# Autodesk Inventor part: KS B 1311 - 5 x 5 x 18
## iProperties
IsCustomPart: 0
Created: 2009-02
Part Number: KS B 1311 - 5 x 5 x 18
Material: 강, 연강
Description: 키 및 해당 키홈
Document SubType Name: Modeling
Standard: KS B 1311
Designer: KYOUNG IL JANG
Standards Organization: KS
Language: ko-KR
Size Designation: 5 x 5 x 18
Categories: <MemberInstance><Categories><Category DisplayName="샤프트 부품" InternalName="7f7aeb1f-a693-4053-b835-cee3144e0d98" Mnemonic="SHFT"><Category DisplayName="키" Interna
Density: 7.86 g/cm^3
Mass: 3.27476 g
Surface Area: 3.57848 cm^2
Volume: 0.416636 cm^3
Author: KYOUNG IL JANG
